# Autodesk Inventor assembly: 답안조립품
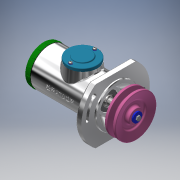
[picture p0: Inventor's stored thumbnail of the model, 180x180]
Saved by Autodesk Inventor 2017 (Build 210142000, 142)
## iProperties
Part Number: 답안조립품
Material: 일반
Document SubType Name: Assembly
Designer: Administrator
Author: Administrator
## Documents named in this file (22)
- C:\Users\Administrator\Desktop\720506V1003\답안조립품.iam
- C:\Users\Administrator\Desktop\720506V1003\본체.ipt
- C:\Users\Administrator\Desktop\720506V1003\개스킷.ipt
- C:\Users\Administrator\Desktop\720506V1003\사이드 커버.ipt
- 사이드 커버.ipt
- C:\Users\Administrator\Desktop\720506V1003\축.ipt
- C:\Users\Administrator\Desktop\720506V1003\멈춤링 15 x 1.ipt
- C:\Users\Administrator\Desktop\720506V1003\멈춤링 35 x 1.6.ipt
- C:\Users\Administrator\Desktop\720506V1003\베어링 6202.ipt
- C:\Users\Administrator\Desktop\720506V1003\부시1.ipt
- C:\Users\Administrator\Desktop\720506V1003\부시2.ipt
- C:\Users\Administrator\Desktop\720506V1003\와셔 10 x 21.ipt
- C:\Users\Administrator\Desktop\720506V1003\너트 M10.ipt
- C:\Users\Administrator\Desktop\720506V1003\오일 실 15 x 30 x 7.ipt
- C:\Users\Administrator\Desktop\720506V1003\키 4 x 4.ipt
- C:\Users\Administrator\Desktop\720506V1003\V-벨트풀리.ipt
- C:\Users\Administrator\Desktop\720506V1003\멈춤나사 M3.ipt
- C:\Users\Administrator\Desktop\720506V1003\와셔 4 x 16.ipt
- C:\Users\Administrator\Desktop\720506V1003\볼트 M4 x 10.ipt
- C:\Users\Administrator\Desktop\720506V1003\탑 커버.ipt
- C:\Users\Administrator\Desktop\720506V1003\와셔 3 x 6.ipt
- C:\Users\Administrator\Desktop\720506V1003\십자볼트 M3 x 10.ipt
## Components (3 placed, 3 different names)
1. 개스킷:1
2. V-벨트풀리:1
3. ISO 4017 M4 x 10:1
